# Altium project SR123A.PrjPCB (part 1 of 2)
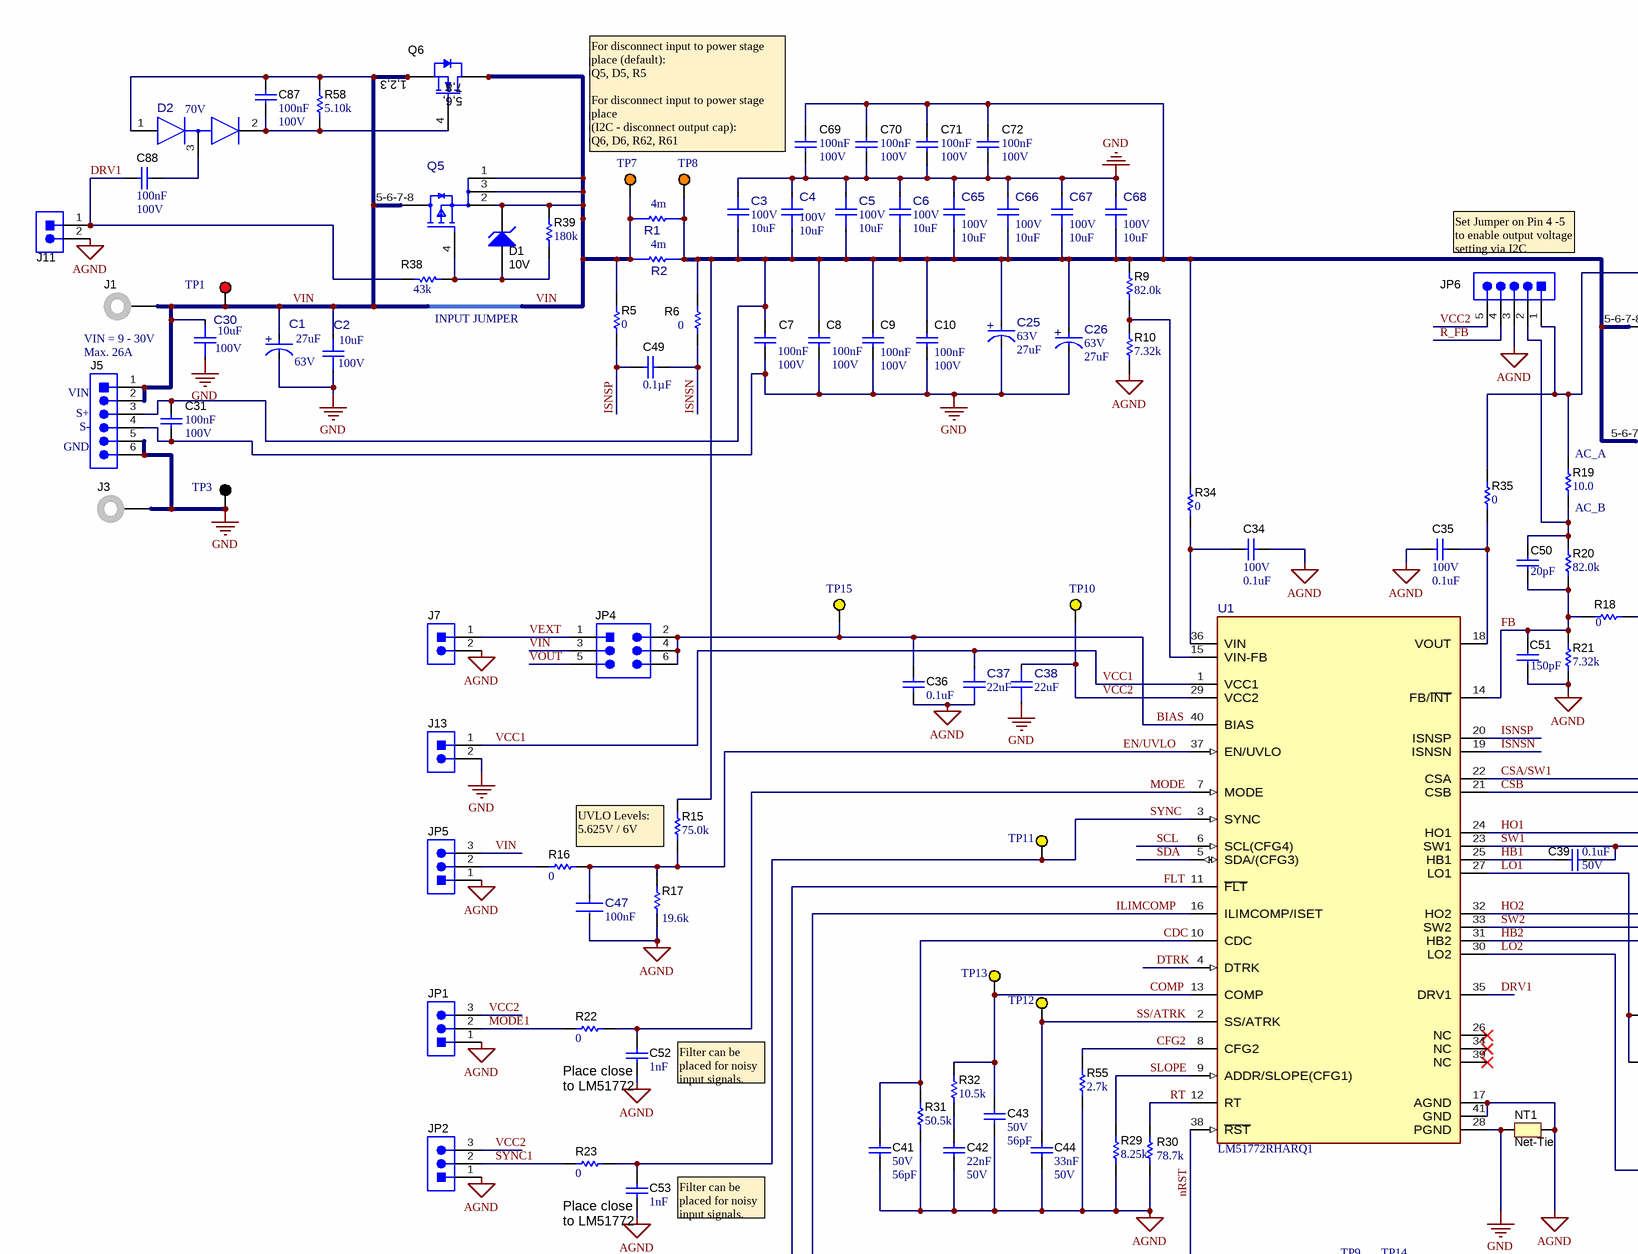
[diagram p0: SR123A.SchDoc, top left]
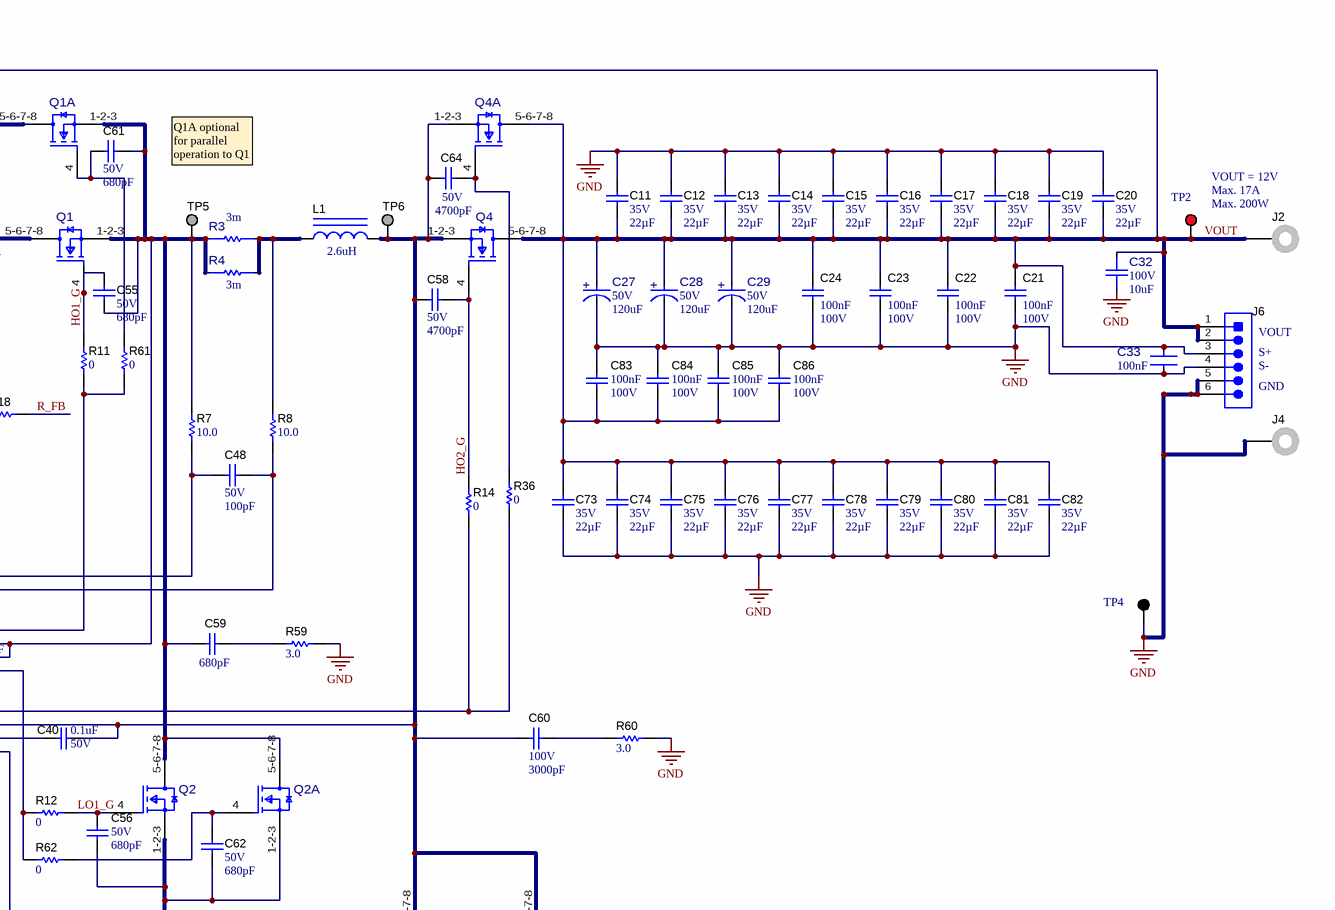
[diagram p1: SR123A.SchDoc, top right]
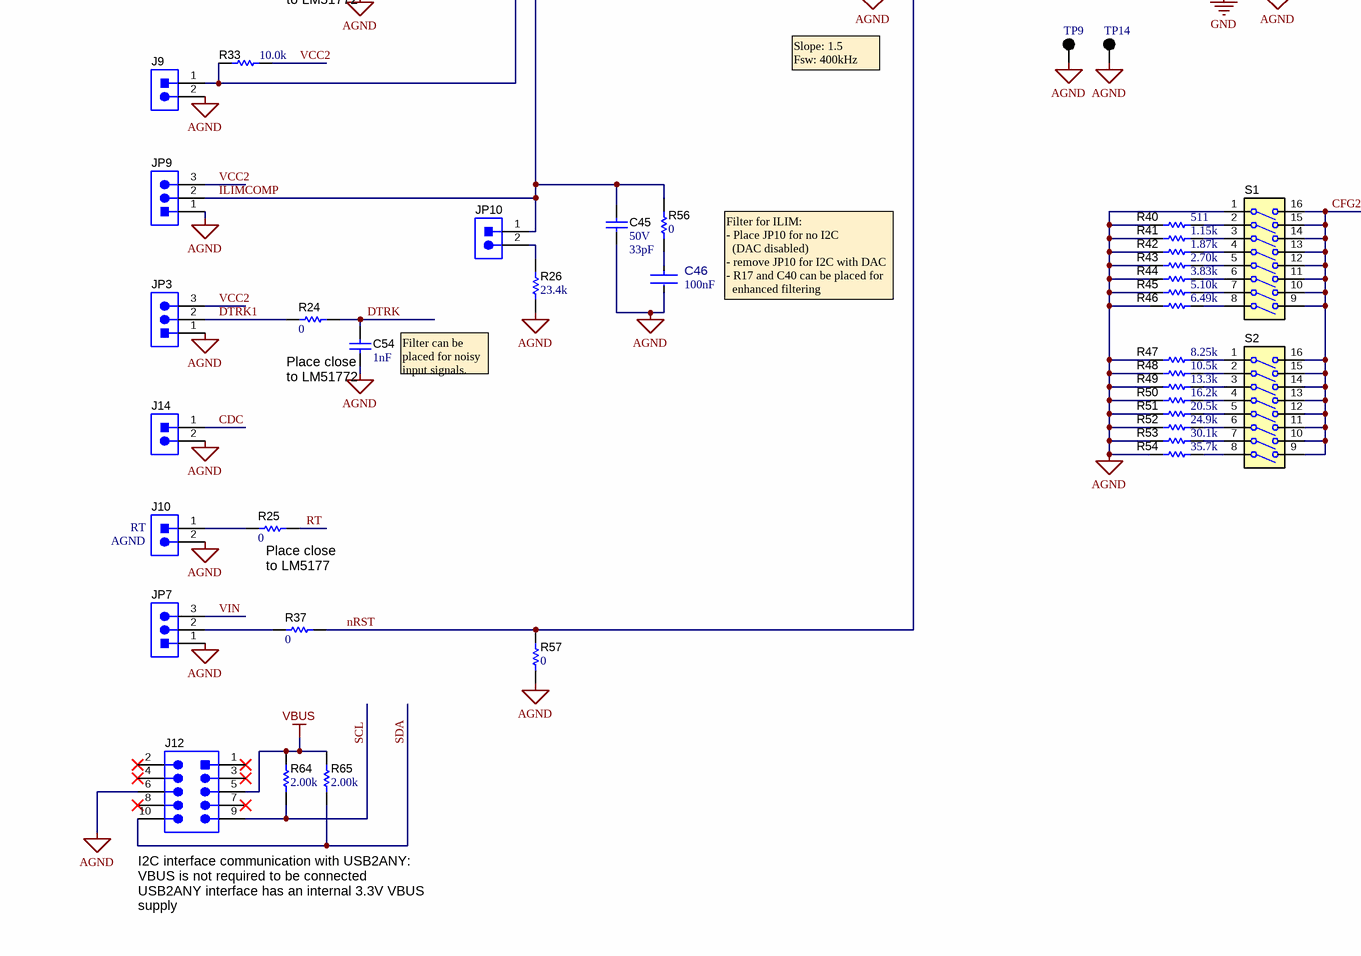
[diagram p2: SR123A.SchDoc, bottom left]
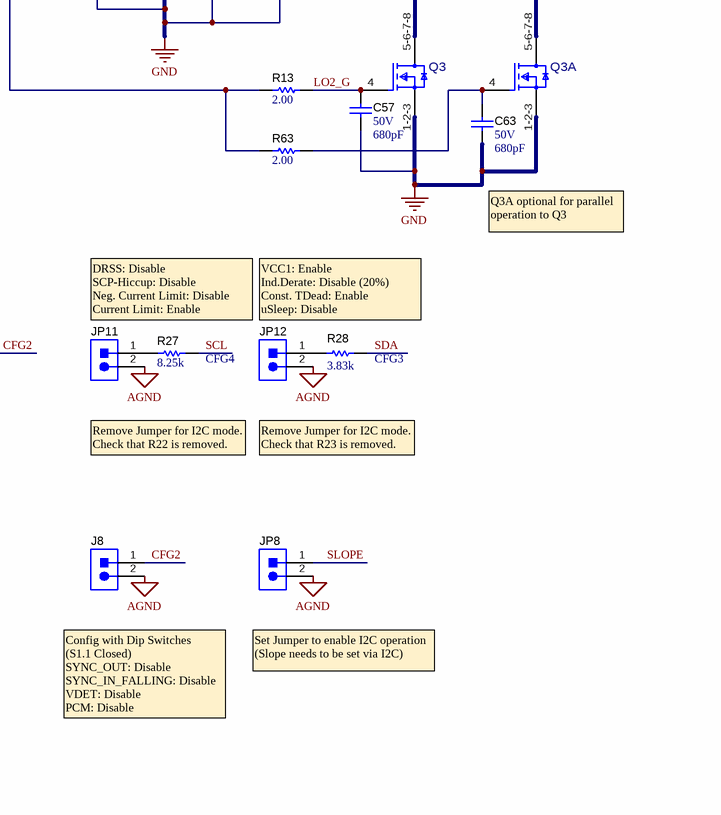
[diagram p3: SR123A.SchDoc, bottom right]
TID: N/A; TechSupport: http://www.ti.com/support; SCH_Rev: A; PRJ_Title: LM51772Q1EVM-HP; PRJ_Number: SR123; PRJ_Customer: Public Release; PCB_Rev: A; CopyrightYear: 2025
3 sheets, 296 parts. Net scope: global (net labels, ports and power ports of the same name join across sheets).
Board file: SR123A.PcbDoc
Sheets:
  SR123A.SchDoc
  SR123A_OptExtLogic.SchDoc
  SR123A_Hardware.SchDoc

## Sheet SR123A.SchDoc: LM51772RWE EVM Schematic
size 558 x 431 mm; Date: Not shown in title block; ApprovedBy: Not shown in title block; CheckedBy: Not shown in title block; Author: Not shown in title block; CompanyName: Not shown in title block; Engineer: Not shown in title block; Organization: Not shown in title block; Address1: Not shown in title block; Address2: Not shown in title block; Address3: Not shown in title block; Address4: Not shown in title block; DocumentNumber: 1; Revision: Use project parameter SCH_Rev; SheetNumber: 1; SheetTotal: 3; PageSetup: Record=PageOptions¦CenterHorizontal=True¦CenterVertical=True¦PrintScale=1.00¦XCorrection=1.00¦YCorrection=1.00¦PrintKind=0¦BorderSize=5000000¦LeftOffset=0¦BottomOffset=0¦Orientation=2¦PaperLength=1000¦PaperWidth=1000¦Scale=100¦PaperSource=15¦PrintQuality=600¦MediaType=1¦DitherType=10¦PaperKind=Letter¦PrintScaleMode=1

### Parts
C1  VDC_V: 63V  ValueDisplayed: 27uF  [FP-A768KE276M1JLAE054_SMT_CAP_8MM3_8MM3-0]  (hidden comment: A768KE276M1JLAE054)
C2  VDC_V: 100V  ValueDisplayed: 10uF  [FP-C3225X7R2A106K250AC_1210-MFG]  (hidden comment: C3225X7R2A106K250AC)
C3  VDC_V: 100V  ValueDisplayed: 10uF  [FP-C3225X7R2A106K250AC_1210-MFG]  (hidden comment: C3225X7R2A106K250AC)
C4  VDC_V: 100V  ValueDisplayed: 10uF  [FP-C3225X7R2A106K250AC_1210-MFG]  (hidden comment: C3225X7R2A106K250AC)
C5  VDC_V: 100V  ValueDisplayed: 10uF  [FP-C3225X7R2A106K250AC_1210-MFG]  (hidden comment: C3225X7R2A106K250AC)
C6  VDC_V: 100V  ValueDisplayed: 10uF  [FP-C3225X7R2A106K250AC_1210-MFG]  (hidden comment: C3225X7R2A106K250AC)
C7  Cap_F: 100nF  VDC_V: 100V  [0603S]  (hidden comment: GCJ188R72A104KA01D)
C8  Cap_F: 100nF  VDC_V: 100V  [0603S]  (hidden comment: GCJ188R72A104KA01D)
C9  Cap_F: 100nF  VDC_V: 100V  [0603S]  (hidden comment: GCJ188R72A104KA01D)
C10  Cap_F: 100nF  VDC_V: 100V  [0603S]  (hidden comment: GCJ188R72A104KA01D)
C11  VDC_V: 35V  ValueDisplayed: 22µF  [1210L]  (hidden comment: GMK325BJ226MM-P)
C12  VDC_V: 35V  ValueDisplayed: 22µF  [1210L]  (hidden comment: GMK325BJ226MM-P)
C13  VDC_V: 35V  ValueDisplayed: 22µF  [1210L]  (hidden comment: GMK325BJ226MM-P)
C14  VDC_V: 35V  ValueDisplayed: 22µF  [1210L]  (hidden comment: GMK325BJ226MM-P)
C15  VDC_V: 35V  ValueDisplayed: 22µF  [1210L]  (hidden comment: GMK325BJ226MM-P)
C16  VDC_V: 35V  ValueDisplayed: 22µF  [1210L]  (hidden comment: GMK325BJ226MM-P)
C17  VDC_V: 35V  ValueDisplayed: 22µF  [1210L]  (hidden comment: GMK325BJ226MM-P)
C18  VDC_V: 35V  ValueDisplayed: 22µF  [1210L]  (hidden comment: GMK325BJ226MM-P)
C19  VDC_V: 35V  ValueDisplayed: 22µF  [1210L]  (hidden comment: GMK325BJ226MM-P)
C20  VDC_V: 35V  ValueDisplayed: 22µF  [1210L]  (hidden comment: GMK325BJ226MM-P)
C21  Cap_F: 100nF  VDC_V: 100V  [0603S]  (hidden comment: GCJ188R72A104KA01D)
C22  Cap_F: 100nF  VDC_V: 100V  [0603S]  (hidden comment: GCJ188R72A104KA01D)
C23  Cap_F: 100nF  VDC_V: 100V  [0603S]  (hidden comment: GCJ188R72A104KA01D)
C24  Cap_F: 100nF  VDC_V: 100V  [0603S]  (hidden comment: GCJ188R72A104KA01D)
C25  VDC_V: 63V  ValueDisplayed: 27uF  [FP-A768KE276M1JLAE054_SMT_CAP_8MM3_8MM3-0]  (hidden comment: A768KE276M1JLAE054)
C26  VDC_V: 63V  ValueDisplayed: 27uF  [FP-A768KE276M1JLAE054_SMT_CAP_8MM3_8MM3-0]  (hidden comment: A768KE276M1JLAE054)
C27  VDC_V: 50V  ValueDisplayed: 120uF  [FP-A768MS127M1HLAE024_SMT_CAP_10MM3_10MM3-MFG]  (hidden comment: A768MS127M1HLAE024)
C28  VDC_V: 50V  ValueDisplayed: 120uF  [FP-A768MS127M1HLAE024_SMT_CAP_10MM3_10MM3-MFG]  (hidden comment: A768MS127M1HLAE024)
C29  VDC_V: 50V  ValueDisplayed: 120uF  [FP-A768MS127M1HLAE024_SMT_CAP_10MM3_10MM3-MFG]  (hidden comment: A768MS127M1HLAE024)
C30  VDC_V: 100V  ValueDisplayed: 10uF  [FP-C3225X7R2A106K250AC_1210-MFG]  (hidden comment: C3225X7R2A106K250AC)
C31  Cap_F: 100nF  VDC_V: 100V  [0603S]  (hidden comment: GCJ188R72A104KA01D)
C32  VDC_V: 100V  ValueDisplayed: 10uF  [FP-C3225X7R2A106K250AC_1210-MFG]  (hidden comment: C3225X7R2A106K250AC)
C33  Cap_F: 100nF  [FP-GCM188L81H104KA57D_0603-MFG]  (hidden comment: GCM188L81H104KA57D)
C34  VDC_V: 100V  ValueDisplayed: 0.1uF  [0402S]  (hidden comment: GRM155R62A104KE14D)
C35  VDC_V: 100V  ValueDisplayed: 0.1uF  [0402S]  (hidden comment: GRM155R62A104KE14D)
C36  ValueDisplayed: 0.1uF  [0603S]  (hidden comment: CGA3E3X7S2A104K080AB)
C37  ValueDisplayed: 22uF  [0603S]  (hidden comment: GRT188R61A226ME13D)
C38  ValueDisplayed: 22uF  [0603S]  (hidden comment: GRT188R61A226ME13D)
C39  VDC_V: 50V  ValueDisplayed: 0.1uF  [0402S]  (hidden comment: GCM155R71H104KE02D)
C40  VDC_V: 50V  ValueDisplayed: 0.1uF  [0402S]  (hidden comment: GCM155R71H104KE02D)
C41  VDC_V: 50V  ValueDisplayed: 56pF  [0603S]  (hidden comment: 06035A560FAT2A)
C42  Cap_F: 22nF  VDC_V: 50V  [0603S]  (hidden comment: C0603X223K5RACTU)
C43  VDC_V: 50V  ValueDisplayed: 56pF  [0603S]  (hidden comment: 06035A560JAT2A)
C44  Cap_F: 33nF  VDC_V: 50V  [0603S]  (hidden comment: 06035C333JAT2A)
C45  VDC_V: 50V  ValueDisplayed: 33pF  [0603S]  (hidden comment: CL10C330FB8NNNC)
C46  Cap_F: 100nF  [FP-GCM188L81H104KA57D_0603-MFG]  (hidden comment: GCM188L81H104KA57D)
C47  Cap_F: 100nF  [FP-GCM188L81H104KA57D_0603-MFG]  (hidden comment: GCM188L81H104KA57D)
C48  VDC_V: 50V  ValueDisplayed: 100pF  [0402S]  (hidden comment: GRM1555C1H101JA01D)
C49  ValueDisplayed: 0.1µF  [0402S]  (hidden comment: 0402BB104KW500)
C50  ValueDisplayed: 20pF  [0603S]  (hidden comment: GRM1885C2A200JA01D)
C51  ValueDisplayed: 150pF  [0603S]  (hidden comment: GRM1885C1H151JA01D)
C52  Cap_F: 1nF  [0603S]  (hidden comment: 06031C102JAT2A)
C53  Cap_F: 1nF  [0603S]  (hidden comment: 06031C102JAT2A)
C54  Cap_F: 1nF  [0603S]  (hidden comment: 06031C102JAT2A)
C55  VDC_V: 50V  ValueDisplayed: 680pF  [0402S]  (hidden comment: GCM1555C1H681FA16D)
C56  VDC_V: 50V  ValueDisplayed: 680pF  [0402S]  (hidden comment: GCM1555C1H681FA16D)
C57  VDC_V: 50V  ValueDisplayed: 680pF  [0402S]  (hidden comment: GCM1555C1H681FA16D)
C58  VDC_V: 50V  ValueDisplayed: 4700pF  [0402S]  (hidden comment: GRM155R71H472KA01D)
C59  ValueDisplayed: 680pF  [0805_HV1]  (hidden comment: GRM2195C2A681JA01D)
C60  VDC_V: 100V  ValueDisplayed: 3000pF  [0805_HV1]  (hidden comment: GRM2165C2A302JA01D)
C61  VDC_V: 50V  ValueDisplayed: 680pF  [0402S]  (hidden comment: GCM1555C1H681FA16D)
C62  VDC_V: 50V  ValueDisplayed: 680pF  [0402S]  (hidden comment: GCM1555C1H681FA16D)
C63  VDC_V: 50V  ValueDisplayed: 680pF  [0402S]  (hidden comment: GCM1555C1H681FA16D)
C64  VDC_V: 50V  ValueDisplayed: 4700pF  [0402S]  (hidden comment: GRM155R71H472KA01D)
C65  VDC_V: 100V  ValueDisplayed: 10uF  [FP-C3225X7R2A106K250AC_1210-MFG]  (hidden comment: C3225X7R2A106K250AC)
C66  VDC_V: 100V  ValueDisplayed: 10uF  [FP-C3225X7R2A106K250AC_1210-MFG]  (hidden comment: C3225X7R2A106K250AC)
C67  VDC_V: 100V  ValueDisplayed: 10uF  [FP-C3225X7R2A106K250AC_1210-MFG]  (hidden comment: C3225X7R2A106K250AC)
C68  VDC_V: 100V  ValueDisplayed: 10uF  [FP-C3225X7R2A106K250AC_1210-MFG]  (hidden comment: C3225X7R2A106K250AC)
C69  Cap_F: 100nF  VDC_V: 100V  [0603S]  (hidden comment: GCJ188R72A104KA01D)
C70  Cap_F: 100nF  VDC_V: 100V  [0603S]  (hidden comment: GCJ188R72A104KA01D)
C71  Cap_F: 100nF  VDC_V: 100V  [0603S]  (hidden comment: GCJ188R72A104KA01D)
C72  Cap_F: 100nF  VDC_V: 100V  [0603S]  (hidden comment: GCJ188R72A104KA01D)
C73  VDC_V: 35V  ValueDisplayed: 22µF  [1210L]  (hidden comment: GMK325BJ226MM-P)
C74  VDC_V: 35V  ValueDisplayed: 22µF  [1210L]  (hidden comment: GMK325BJ226MM-P)
C75  VDC_V: 35V  ValueDisplayed: 22µF  [1210L]  (hidden comment: GMK325BJ226MM-P)
C76  VDC_V: 35V  ValueDisplayed: 22µF  [1210L]  (hidden comment: GMK325BJ226MM-P)
C77  VDC_V: 35V  ValueDisplayed: 22µF  [1210L]  (hidden comment: GMK325BJ226MM-P)
C78  VDC_V: 35V  ValueDisplayed: 22µF  [1210L]  (hidden comment: GMK325BJ226MM-P)
C79  VDC_V: 35V  ValueDisplayed: 22µF  [1210L]  (hidden comment: GMK325BJ226MM-P)
C80  VDC_V: 35V  ValueDisplayed: 22µF  [1210L]  (hidden comment: GMK325BJ226MM-P)
C81  VDC_V: 35V  ValueDisplayed: 22µF  [1210L]  (hidden comment: GMK325BJ226MM-P)
C82  VDC_V: 35V  ValueDisplayed: 22µF  [1210L]  (hidden comment: GMK325BJ226MM-P)
C83  Cap_F: 100nF  VDC_V: 100V  [0603S]  (hidden comment: GCJ188R72A104KA01D)
C84  Cap_F: 100nF  VDC_V: 100V  [0603S]  (hidden comment: GCJ188R72A104KA01D)
C85  Cap_F: 100nF  VDC_V: 100V  [0603S]  (hidden comment: GCJ188R72A104KA01D)
C86  Cap_F: 100nF  VDC_V: 100V  [0603S]  (hidden comment: GCJ188R72A104KA01D)
C87  Cap_F: 100nF  VDC_V: 100V  [0603S]  (hidden comment: GCJ188R72A104KA01D)
C88  Cap_F: 100nF  VDC_V: 100V  [0603S]  (hidden comment: GCJ188R72A104KA01D)
D1  value 10V  [SOD-123]  (hidden comment: MMSZ4697T1G)
D2  Vf_V: 70V  [FP-BAS70-04-E3-18_SOT23-3-MFG]  (hidden comment: BAS70-04-E3-18)
J1  108-0740-001  [Johnson_108-0740-001]  (value not drawn)
J2  108-0740-001  [Johnson_108-0740-001]  (value not drawn)
J3  108-0740-001  [Johnson_108-0740-001]  (value not drawn)
J4  108-0740-001  [Johnson_108-0740-001]  (value not drawn)
J5  61300611121  [WURTH_61300611121]  (value not drawn)
J6  61300611121  [WURTH_61300611121]  (value not drawn)
J7  61300211121  [WURTH_61300211121]  (value not drawn)
J8  61300211121  [WURTH_61300211121]  (value not drawn)
J9  61300211121  [WURTH_61300211121]  (value not drawn)
J10  61300211121  [WURTH_61300211121]  (value not drawn)
J11  61300211121  [WURTH_61300211121]  (value not drawn)
J12  N2510-6002-RB  [CONN_2510-6002]  (value not drawn)
J13  61300211121  [WURTH_61300211121]  (value not drawn)
J14  61300211121  [WURTH_61300211121]  (value not drawn)
JP1  61300311121  [WURTH_61300311121]  (value not drawn)
JP2  61300311121  [WURTH_61300311121]  (value not drawn)
JP3  61300311121  [WURTH_61300311121]  (value not drawn)
JP4  HTSW-103-07-G-D  [Samtec_HTSW-103-07-x-D]  (value not drawn)
JP5  61300311121  [WURTH_61300311121]  (value not drawn)
JP6  61300511121  [Wurth_61300511121]  (value not drawn)
JP7  61300311121  [WURTH_61300311121]  (value not drawn)
JP8  61300211121  [WURTH_61300211121]  (value not drawn)
JP9  61300311121  [WURTH_61300311121]  (value not drawn)
JP10  61300211121  [WURTH_61300211121]  (value not drawn)
JP11  61300211121  [WURTH_61300211121]  (value not drawn)
JP12  61300211121  [WURTH_61300211121]  (value not drawn)
L1  ValueDisplayed: 2.6uH  [WE-HCB_1890]  (hidden comment: 7443556260)
NT1  Net-Tie  [Net-Tie_10mil]  (net tie, no BOM)
Q1  IAUCN04S7L014ATMA1  [FP-IAUCN04S7L014ATMA1_TDSON8-MFG]  (value not drawn)
Q1A  IAUCN04S7L014ATMA1  [FP-IAUCN04S7L014ATMA1_TDSON8-MFG]  (value not drawn)
Q2  IAUCN04S7L014ATMA1  [FP-IAUCN04S7L014ATMA1_TDSON8-MFG]  (value not drawn)
Q2A  IAUCN04S7L014ATMA1  [FP-IAUCN04S7L014ATMA1_TDSON8-MFG]  (value not drawn)
Q3  IAUCN04S7L014ATMA1  [FP-IAUCN04S7L014ATMA1_TDSON8-MFG]  (value not drawn)
Q3A  IAUCN04S7L014ATMA1  [FP-IAUCN04S7L014ATMA1_TDSON8-MFG]  (value not drawn)
Q4  IAUCN04S7L014ATMA1  [FP-IAUCN04S7L014ATMA1_TDSON8-MFG]  (value not drawn)
Q4A  IAUCN04S7L014ATMA1  [FP-IAUCN04S7L014ATMA1_TDSON8-MFG]  (value not drawn)
Q5  SI7155DP-T1-GE3  [FP-SI7155DP-T1-GE3_PowerPAK-SO8-MFG]  (value not drawn)
Q6  CSD18540Q5B  [DNK0008A]  (value not drawn)
R1  value 4m  [FP-KRL2012E-M-R004-F-T5_2012-MFG]  (hidden comment: KRL2012E-M-R004-F-T5)
R2  value 4m  [FP-KRL2012E-M-R004-F-T5_2012-MFG]  (hidden comment: KRL2012E-M-R004-F-T5)
R3  value 3m  [FP-KRL2012E-M-R003-F-T5_0805-MFG]  (hidden comment: KRL2012E-M-R003-F-T5)
R4  value 3m  [FP-KRL2012E-M-R003-F-T5_0805-MFG]  (hidden comment: KRL2012E-M-R003-F-T5)
R5  ValueDisplayed: 0  [0603S]  (hidden comment: RMCF0603ZT0R00)
R6  ValueDisplayed: 0  [0603S]  (hidden comment: RMCF0603ZT0R00)
R7  ValueDisplayed: 10.0  [0603S]  (hidden comment: CRCW060310R0FKEAHP)
R8  ValueDisplayed: 10.0  [0603S]  (hidden comment: CRCW060310R0FKEAHP)
R9  ValueDisplayed: 82.0k  [0603S]  (hidden comment: RC0603FR-0782KL)
R10  ValueDisplayed: 7.32k  [0603S]  (hidden comment: CRCW06037K32FKEA)
R11  ValueDisplayed: 0  [0603S]  (hidden comment: RMCF0603ZT0R00)
R12  ValueDisplayed: 0  [0603S]  (hidden comment: RMCF0603ZT0R00)
R13  ValueDisplayed: 2.00  [0603S]  (hidden comment: MCT06030C2008FP500)
R14  ValueDisplayed: 0  [0603S]  (hidden comment: RMCF0603ZT0R00)
R15  ValueDisplayed: 75.0k  [0603S]  (hidden comment: RC0603FR-0775KL)
R16  ValueDisplayed: 0  [0603S]  (hidden comment: RMCF0603ZT0R00)
R17  ValueDisplayed: 19.6k  [0603S]  (hidden comment: CRCW060319K6FKEA)
R18  ValueDisplayed: 0  [0603S]  (hidden comment: RMCF0603ZT0R00)
R19  ValueDisplayed: 10.0  [0603S]  (hidden comment: RC0603FR-0710RL)
R20  ValueDisplayed: 82.0k  [0603S]  (hidden comment: RC0603FR-0782KL)
R21  ValueDisplayed: 7.32k  [0603S]  (hidden comment: CRCW06037K32FKEA)
R22  ValueDisplayed: 0  [0603S]  (hidden comment: RMCF0603ZT0R00)
R23  ValueDisplayed: 0  [0603S]  (hidden comment: RMCF0603ZT0R00)
R24  ValueDisplayed: 0  [0603S]  (hidden comment: RMCF0603ZT0R00)
R25  ValueDisplayed: 0  [0603S]  (hidden comment: RMCF0603ZT0R00)
R26  ValueDisplayed: 23.4k  [0603S]  (hidden comment: RT0603BRD0723K4L)
R27  ValueDisplayed: 8.25k  [0603S]  (hidden comment: RC0603FR-078K25L)
R28  ValueDisplayed: 3.83k  [0603S]  (hidden comment: CRCW06033K83FKEA)
R29  ValueDisplayed: 8.25k  [0603S]  (hidden comment: RC0603FR-078K25L)
R30  ValueDisplayed: 78.7k  [0603S]  (hidden comment: CRCW060378K7FKEA)
R31  ValueDisplayed: 50.5k  [0603S]  (hidden comment: RT0603BRD0750K5L)
R32  ValueDisplayed: 10.5k  [0603S]  (hidden comment: CRCW060310K5FKEA)
R33  ValueDisplayed: 10.0k  [0603S]  (hidden comment: RT0603BRD0710KL)
R34  ValueDisplayed: 0  [0603S]  (hidden comment: RMCF0603ZT0R00)
R35  ValueDisplayed: 0  [0603S]  (hidden comment: RMCF0603ZT0R00)
R36  ValueDisplayed: 0  [0603S]  (hidden comment: RMCF0603ZT0R00)
R37  ValueDisplayed: 0  [0603S]  (hidden comment: RMCF0603ZT0R00)
R38  ValueDisplayed: 43k  [0603S]  (hidden comment: CRCW060343K0JNEA)
R39  ValueDisplayed: 180k  [0603S]  (hidden comment: CRCW0603180KJNEA)
R40  ValueDisplayed: 511  [0603S]  (hidden comment: CRCW0603511RFKEA)
R41  ValueDisplayed: 1.15k  [0603S]  (hidden comment: CRCW06031K15FKEA)
R42  ValueDisplayed: 1.87k  [0603S]  (hidden comment: RC0603FR-071K87L)
R43  ValueDisplayed: 2.70k  [0603S]  (hidden comment: RC0603FR-072K7L)
R44  ValueDisplayed: 3.83k  [0603S]  (hidden comment: CRCW06033K83FKEA)
R45  ValueDisplayed: 5.10k  [0603S]  (hidden comment: RC0603FR-075K1L)
R46  ValueDisplayed: 6.49k  [0603S]  (hidden comment: RC0603FR-076K49L)
R47  ValueDisplayed: 8.25k  [0603S]  (hidden comment: RC0603FR-078K25L)
R48  ValueDisplayed: 10.5k  [0603S]  (hidden comment: CRCW060310K5FKEA)
R49  ValueDisplayed: 13.3k  [0603S]  (hidden comment: RC0603FR-0713K3L)
R50  ValueDisplayed: 16.2k  [0603S]  (hidden comment: CRCW060316K2FKEA)
R51  ValueDisplayed: 20.5k  [0603S]  (hidden comment: RC0603FR-0720K5L)
R52  ValueDisplayed: 24.9k  [0603S]  (hidden comment: CRCW060324K9FKEA)
R53  ValueDisplayed: 30.1k  [0603S]  (hidden comment: CRCW060330K1FKEA)
R54  ValueDisplayed: 35.7k  [0603S]  (hidden comment: CRCW060335K7FKEA)
R55  ValueDisplayed: 2.7k  [0603S]  (hidden comment: CRCW06032K70JNEA)
R56  ValueDisplayed: 0  [0603S]  (hidden comment: RMCF0603ZT0R00)
R57  ValueDisplayed: 0  [0603S]  (hidden comment: RMCF0603ZT0R00)
R58  ValueDisplayed: 5.10k  [0603S]  (hidden comment: RC0603FR-075K1L)
R59  ValueDisplayed: 3.0  [0603S]  (hidden comment: CRCW06033R00JNEA)
R60  ValueDisplayed: 3.0  [0603S]  (hidden comment: CRCW06033R00JNEA)
R61  ValueDisplayed: 0  [0603S]  (hidden comment: RMCF0603ZT0R00)
R62  ValueDisplayed: 0  [0603S]  (hidden comment: RMCF0603ZT0R00)
R63  ValueDisplayed: 2.00  [0603S]  (hidden comment: MCT06030C2008FP500)
R64  ValueDisplayed: 2.00k  [0603S]  (hidden comment: RC0603FR-072KL)
R65  ValueDisplayed: 2.00k  [0603S]  (hidden comment: RC0603FR-072KL)
S1  218-8LPST  [SW_218-8LP]  (value not drawn)
S2  218-8LPST  [SW_218-8LP]  (value not drawn)
TP1  5010  [Keystone5010]  (value not drawn)
TP2  5010  [Keystone5010]  (value not drawn)
TP3  5011  [Keystone5011]  (value not drawn)
TP4  5011  [Keystone5011]  (value not drawn)
TP5  S2761-46R  [Harwin_S2761-46R]  (value not drawn)
TP6  S2761-46R  [Harwin_S2761-46R]  (value not drawn)
TP7  5013  [Keystone5013]  (value not drawn)
TP8  5013  [Keystone5013]  (value not drawn)
TP9  5001  [Keystone5001]  (value not drawn)
TP10  5004  [Keystone5004]  (value not drawn)
TP11  5004  [Keystone5004]  (value not drawn)
TP12  5004  [Keystone5004]  (value not drawn)
TP13  5004  [Keystone5004]  (value not drawn)
TP14  5001  [Keystone5001]  (value not drawn)
TP15  5004  [Keystone5004]  (value not drawn)
U1  LM51772RHARQ1  [RHA0040P-MFG]

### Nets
AGND: C34.1 C35.2 C36.1 C37.1 C41.2 C42.2 C43.2 C44.2 C45.2 C46.2 C47.2 C51.2 C52.2 C53.2 C54.2 J7.2 J8.2 J9.2 J10.2 J11.2 J12.6 J14.2 JP1.1 JP2.1 JP3.1 JP5.1 JP6.3 JP7.1 JP8.2 JP9.1 JP11.2 JP12.2 NT1.2 R10.1 R17.1 R21.1 R26.1 R29.1 R30.1 R31.1 R40.1 R41.1 R42.1 R43.1 R44.1 R45.1 R46.1 R47.1 R48.1 R49.1 R50.1 R51.1 R52.1 R53.1 R54.1 R55.1 R57.2 S1.1 TP9.1 TP14.1 U1.17(AGND) U1.41(GND)
GND: C1.1(CATHODE) C2.1 C3.2 C4.2 C5.2 C6.2 C7.2 C8.2 C9.2 C10.2 C11.1 C12.1 C13.1 C14.1 C15.2 C16.2 C17.2 C18.2 C19.2 C20.2 C21.2 C22.2 C23.2 C24.2 C25.1(CATHODE) C26.1(CATHODE) C27.1(CATHODE) C28.1(CATHODE) C29.1(CATHODE) C30.1 C31.2 C32.1 C33.2 C38.1 C56.2 C57.2 C62.2 C63.2 C65.2 C66.2 C67.2 C68.2 C69.2 C70.2 C71.2 C72.2 C73.1 C74.1 C75.1 C76.1 C77.2 C78.1 C79.2 C80.2 C81.1 C82.2 C83.1 C84.1 C85.1 C86.1 J3.1 J4.1 J5.4 J5.5 J5.6 J6.4 J6.5 J6.6 J13.2 NT1.1 Q2.1-2-3(S) Q2A.1-2-3(S) Q3.1-2-3(S) Q3A.1-2-3(S) R59.1 R60.1 TP3.1 TP4.1 U1.28(PGND)
VBUS: J12.5 R64.2 R65.2
VCC1: C37.2 J13.1 U1.1(VCC1)
BIAS: C36.2 JP4.2 JP4.4 JP4.6 TP15.1 U1.40(BIAS)
CDC: C41.1 J14.1 R31.2 U1.10(CDC)
CFG2: J8.1 R55.2 S1.9(8A) S1.10(7A) S1.11(6A) S1.12(5A) S1.13(4A) S1.14(3A) S1.15(2A) S1.16(1A) S2.9(8A) S2.10(7A) S2.11(6A) S2.12(5A) S2.13(4A) S2.14(3A) S2.15(2A) S2.16(1A) U1.8(CFG2)
COMP: C43.1 R32.2 TP13.1 U1.13(COMP)
CSA/SW1: C48.2 R7.1 U1.22(CSA)
CSB: C48.1 R8.1 U1.21(CSB)
DRV1: C88.1 J11.1 R38.1 U1.35(DRV1)
DTRK: C54.1 R24.2 U1.4(DTRK)
DTRK1: JP3.2 R24.1
EN/UVLO: C47.1 R15.1 R16.1 R17.2 U1.37(EN/UVLO)
FB: C50.2 C51.1 R18.1 R20.1 R21.2 U1.14(FB/~{INT})
FLT: J9.1 R33.1 U1.11(~{FLT})
HB1: C39.2 U1.25(HB1)
HB2: C40.2 U1.31(HB2)
HO1: R11.1 R61.1 U1.24(HO1)
HO1_G: C55.1 Q1.4(G) R11.2
HO2: R14.1 R36.1 U1.32(HO2)
HO2_G: C58.2 Q4.4(G) R14.2
ILIMCOMP: C45.1 JP9.2 JP10.1 R56.2 U1.16(ILIMCOMP/ISET)
ISNSN: C49.1 R6.1 U1.19(ISNSN)
ISNSP: C49.2 R5.1 U1.20(ISNSP)
LO1: R12.1 R62.1 U1.27(LO1)
LO1_G: C56.1 Q2.4(G) R12.2
LO2: R13.1 R63.1 U1.30(LO2)
LO2_G: C57.1 Q3.4(G) R13.2
MODE: C52.1 R22.2 U1.7(MODE)
MODE1: JP1.2 R22.1
nRST: R37.1 R57.1 U1.38(~{RST})
R_FB: JP6.4 R18.2
RT: R25.1 R30.2 U1.12(RT)
SCL: J12.9 R27.2 R64.1 U1.6(SCL(CFG4))
SDA: J12.10 R28.2 R65.1 U1.5(SDA/(CFG3))
SLOPE: JP8.1 R29.2 U1.9(ADDR/SLOPE(CFG1))
SS/ATRK: C44.1 TP12.1 U1.2(SS/ATRK)
SW1: C39.1 C55.2 C59.2 C61.2 Q1.1-2-3(S) Q1A.1-2-3(S) Q2.5-6-7-8(D) Q2A.5-6-7-8(D) R3.1 R4.1 R7.2 TP5.1 U1.23(SW1)
SW2: C40.1 C58.1 C60.2 C64.1 L1.2 Q3.5-6-7-8(D) Q3A.5-6-7-8(D) Q4.1-2-3(S) Q4A.1-2-3(S) TP6.1 U1.33(SW2)
SYNC: C53.1 R23.2 TP11.1 U1.3(SYNC)
SYNC1: JP2.2 R23.1
VCC2: C38.2 JP1.3 JP2.3 JP3.3 JP6.5 JP9.3 R33.2 TP10.1 U1.29(VCC2)
VEXT: J7.1 JP4.1
VIN: C1.2(ANODE) C2.2 C30.2 C87.2 D1.1(K) D2.1(1_ANODE) J1.1 J5.1 J5.2 JP4.3 JP5.3 JP7.3 Q5.1(S) Q5.2(S) Q5.3(S) Q5.5-6-7-8(D) Q6.1(S) Q6.2(S) Q6.3(S) Q6.5(D) Q6.6(D) Q6.7(D) Q6.8(D) Q6.9(D) R1.1 R2.1 R5.2 R39.2 R58.2 TP1.1 TP7.1
VOUT: C11.2 C12.2 C13.2 C14.2 C15.1 C16.1 C17.1 C18.1 C19.1 C20.1 C21.1 C22.1 C23.1 C24.1 C27.2(ANODE) C28.2(ANODE) C29.2(ANODE) C32.2 C33.1 C73.2 C74.2 C75.2 C76.2 C77.1 C78.2 C79.1 C80.1 C81.2 C82.1 C83.2 C84.2 C85.2 C86.2 J2.1 J6.1 J6.2 J6.3 JP4.5 JP6.1 Q4.5-6-7-8(D) Q4A.5-6-7-8(D) R19.2 R35.2 TP2.1
NetC3_1: C3.1 C4.1 C5.1 C6.1 C7.1 C8.1 C9.1 C10.1 C25.2(ANODE) C26.2(ANODE) C31.1 C65.1 C66.1 C67.1 C68.1 C69.1 C70.1 C71.1 C72.1 J5.3 Q1.5-6-7-8(D) Q1A.5-6-7-8(D) R1.2 R2.2 R6.2 R9.2 R15.2 R34.2 TP8.1
NetC34_2: C34.2 R34.1 U1.36(VIN)
NetC35_1: C35.1 R35.1 U1.18(VOUT)
NetC42_1: C42.1 R32.1
NetC46_1: C46.1 R56.1
NetC50_1: C50.1 JP6.2 R19.1 R20.2
NetC59_1: C59.1 R59.2
NetC60_1: C60.1 R60.2
NetC61_1: C61.1 Q1A.4(G) R61.2
NetC62_1: C62.1 Q2A.4(G) R62.2
NetC63_1: C63.1 Q3A.4(G) R63.2
NetC64_2: C64.2 Q4A.4(G) R36.2
NetC87_1: C87.1 D2.2(2_CATHODE) Q6.4(G) R58.1
NetC88_2: C88.2 D2.3(1_CATHODE/2_ANODE)
NetD1_2: D1.2(A) Q5.4(G) R38.2 R39.1
NetJ10_1: J10.1 R25.2
NetJP5_2: JP5.2 R16.2
NetJP7_2: JP7.2 R37.2
NetJP10_2: JP10.2 R26.2
NetJP11_1: JP11.1 R27.1
NetJP12_1: JP12.1 R28.1
NetL1_1: L1.1 R3.2 R4.2 R8.2
NetR9_1: R9.1 R10.2 U1.15(VIN-FB)
NetR40_2: R40.2 S1.2
NetR41_2: R41.2 S1.3
NetR42_2: R42.2 S1.4
NetR43_2: R43.2 S1.5
NetR44_2: R44.2 S1.6
NetR45_2: R45.2 S1.7
NetR46_2: R46.2 S1.8
NetR47_2: R47.2 S2.1
NetR48_2: R48.2 S2.2
NetR49_2: R49.2 S2.3
NetR50_2: R50.2 S2.4
NetR51_2: R51.2 S2.5
NetR52_2: R52.2 S2.6
NetR53_2: R53.2 S2.7
NetR54_2: R54.2 S2.8

Not connected (* = marked no-connect by the designer): J12 1* 2* 3* 4* 7* 8*; U1 26(NC)* 34(NC)* 39(NC)*

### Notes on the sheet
- For disconnect input to power stage place (default):
  Q5, D5, R5
  For disconnect input to power stage place
  (I2C - disconnect output cap):
  Q6, D6, R62, R61
- (near JP6) Set Jumper on Pin 4 -5 to enable output voltage setting via I2C
- VIN = 9 - 30V
- Max. 26A
- (near R38) INPUT JUMPER
- Q1A optional for parallel operation to Q1
- (near J5) VIN
- (near J5) S+
- (near J5) S-
- VOUT = 12V
- Max. 17A
- Max. 200W
- (near J5) GND
- (near R19) AC_A
- (near R19) AC_B
- (near J6) VOUT
- (near J6) S+
- (near J6) S-
- GND
- UVLO Levels:
  5.625V / 6V
- (near C52) Place close
  to LM51772
- (near C52) Filter can be placed for noisy input signals.
- (near C53) Place close
  to LM51772
- (near C53) Filter can be placed for noisy input signals.
- Slope: 1.5
  Fsw: 400kHz
- Q3A optional for parallel operation to Q3
- DRSS: Disable
  SCP-Hiccup: Disable
  Neg. Current Limit: Disable
  Current Limit: Enable
- (near R27) CFG4
- VCC1: Enable
  Ind.Derate: Disable (20%)
  Const. TDead: Enable
  uSleep: Disable
- (near R28) CFG3
- Filter for ILIM:
  - Place JP10 for no I2C
  (DAC disabled)
  - remove JP10 for I2C with DAC
  - R17 and C40 can be placed for
  enhanced filtering
- Remove Jumper for I2C mode.
  Check that R22 is removed.
- Remove Jumper for I2C mode.
  Check that R23 is removed.
- (near C54) Place close
  to LM51772
- Filter can be placed for noisy input signals.
- (near J10) AGND
- (near J10) RT
- (near R25) Place close
  to LM5177
- Config with Dip Switches
  (S1.1 Closed)
  SYNC_OUT: Disable
  SYNC_IN_FALLING: Disable
  VDET: Disable
  PCM: Disable
- Set Jumper to enable I2C operation
  (Slope needs to be set via I2C)
- (near J12) I2C interface communication with USB2ANY:
  VBUS is not required to be connected
  USB2ANY interface has an internal 3.3V VBUS supply

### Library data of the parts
C1 C25 C26 = CMP-0097690-1: Cap Aluminum Polymer 27uF 63V 20% Solder Cylindrical 54m Ohm 1175mA 2000 hr 125°C T/R; Manufacturer: KEMET; Life: 2000Hours; Cap_F: 27µF; Value: 27µF; Leakage Current: 340uA; SizeZ_mm: 7mm; IRMS_A: 1.175A; AEC Qualified: No
C2-C6 C30 C32 C65-C68 = CMP-0096021-1: 10 µF ±10% 100V Ceramic Capacitor X7R 1210 (3225 Metric); Manufacturer: TDK; Cap_F: 10µF; AEC Qualified: No; Value: 10µF; SizeZ_mm: 2.85mm; TempCo: 15%
C7-C10 C21-C24 C31 C69-C72 C83-C88 = CMP-0064935-4: CAP, CERM, 0.1 uF, 100 V,+/- 10%, X7R, AEC-Q200 Grade 1, 0603; Manufacturer: MuRata; TaMin_C: -55°C; Polarized: N; SizeAreaWB_mm2: 4.68; Value1: Unknown; U/M: EA; Value: 0.1uF; TaMax_C: 125°C; SizeZ_mm: 1; SizeX_mm: 1.6; SizeY_mm: 0.8; Cap_Case: 0603; SizeArea_mm2: 1.28; AEC Qualified: Y; AEC Category: Q200
C11-C20 C73-C82 = CMP-0085817-1: CAP, CERM, 22 µF, 35 V,+/- 20%, X5R, 1210; Manufacturer: Taiyo Yuden; Value: 22uF; SizeZ_mm: 1.35; Cap_Case: 1210; TaMax_C: 85°C; U/M: EA; SizeAreaWB_mm2: 14.7; SizeX_mm: 3.2; SizeArea_mm2: 8; TaMin_C: -55°C; AEC Qualified: N; SizeY_mm: 2.5; AEC Category: Q200
C27-C29 = CMP-0097021-1: 120 µF 50 V Aluminum - Polymer Capacitors Radial, Can - SMD 24mOhm 2000 Hrs @ 125°C; Manufacturer: KEMET; Cap_F: 120µF; AEC Qualified: No; IRMS_A: 2.15A; Life: 2000Hours; Value: 120µF; Leakage Current: 1200uA; SizeZ_mm: 12.7mm; Tolerance_%: 20%; Esr: 24m
C33 C46 C47 = CMP-0086535-1: 0.1µF ±10% 50V Ceramic Capacitor X8L 0603 (1608 Metric); Manufacturer: Murata Electronics North America; Symbol Name: SYM-GCM188L81H104KA57D; AEC Qualified: Yes; TempCo: -40+15%; SizeZ_mm: 0.9mm; AEC Grade: Grade 0
C34 C35 = CMP-0006618-2: CAP, CERM, 0.1 uF, 100 V, +/- 10%, X5R, 0402; Manufacturer: MuRata; TaMin_C: -55°C; Polarized: N; SizeAreaWB_mm2: 3; Value1: Unknown; U/M: EA; Value: 0.1uF; TaMax_C: 85°C; SizeZ_mm: 0.6; SizeX_mm: 1; SizeY_mm: 0.5; Cap_Case: 0402; Cap_F: 100nF; AEC Category: Q200
C36 = CMP-0007099-4: CAP, CERM, 0.1 uF, 100 V, +/- 10%, X7S, AEC-Q200 Grade 1, 0603; Manufacturer: TDK; TaMin_C: -55°C; ESR_ohm: 0.04959; Polarized: N; SizeAreaWB_mm2: 4.68; Value1: 0.04959 ohm; U/M: EA; Value: 0.1uF; TaMax_C: 125°C; SizeZ_mm: 1; SizeX_mm: 1.6; SizeY_mm: 0.8; Cap_Case: 0603; Value2: 100V; SizeArea_mm2: 1.28; AEC Qualified: Y; Cap_F: 100nF; IRMS_A: 7.51618dA; AEC Category: Q200
C37 C38 = CMP-0092433-2: Multi-Layer Ceramic Capacitor 22uF 10V X5R ±20% 0603 Paper T/R; Manufacturer: Murata; Cap_F: 22µF; Value: 22µF; SizeZ_mm: 1mm; AEC Qualified: Yes; AEC Grade: Grade 3; TempCo: 15%
C39 C40 = CMP-0006356-2: CAP, CERM, 0.1 uF, 50 V, +/- 10%, X7R, AEC-Q200 Grade 1, 0402; Manufacturer: MuRata; TaMin_C: -55°C; Polarized: N; SizeAreaWB_mm2: 3; Value1: Unknown; U/M: EA; Value: 0.1uF; TaMax_C: 125°C; SizeZ_mm: 0.6; SizeX_mm: 1; SizeY_mm: 0.5; Cap_Case: 0402; AEC Qualified: Y; Cap_F: 100nF; AEC Category: Q200
C41 = CMP-0006792-4: CAP, CERM, 56 pF, 50 V, +/- 1%, C0G/NP0, 0603; Manufacturer: AVX; TaMin_C: -55°C; Polarized: N; SizeAreaWB_mm2: 4.68; Value1: Unknown; U/M: EA; Value: 56pF; TaMax_C: 125°C; SizeZ_mm: 1; SizeX_mm: 1.6; SizeY_mm: 0.8; Cap_Case: 0603; SizeArea_mm2: 1.28; AEC Category: Q200
C42 = CMP-0006984-4: CAP, CERM, 0.022 uF, 50 V, +/- 10%, X7R, 0603; Manufacturer: Kemet; TaMin_C: -55°C; Polarized: N; SizeAreaWB_mm2: 4.68; Value1: Unknown; U/M: EA; TaMax_C: 125°C; SizeZ_mm: 1; SizeX_mm: 1.6; SizeY_mm: 0.8; Cap_Case: 0603; SizeArea_mm2: 1.28; AEC Category: Q200
C43 = CMP-0006793-4: CAP, CERM, 56 pF, 50 V, +/- 5%, C0G/NP0, 0603; Manufacturer: AVX; TaMin_C: -55°C; ESR_ohm: 0.159; Polarized: N; SizeAreaWB_mm2: 4.68; Value1: 0.159 ohm; U/M: EA; Value: 56pF; TaMax_C: 125°C; SizeZ_mm: 1; SizeX_mm: 1.6; SizeY_mm: 0.8; Cap_Case: 0603; SizeArea_mm2: 1.28; AEC Category: Q200
C44 = CMP-0006806-4: CAP, CERM, 0.033 uF, 50 V, +/- 5%, X7R, 0603; Manufacturer: AVX; TaMin_C: -55°C; Polarized: N; SizeAreaWB_mm2: 4.68; Value1: Unknown; U/M: EA; TaMax_C: 125°C; SizeZ_mm: 1; SizeX_mm: 1.6; SizeY_mm: 0.8; Cap_Case: 0603; SizeArea_mm2: 1.28; AEC Category: Q200
C45 = CMP-0007117-4: CAP, CERM, 33 pF, 50 V, +/- 5%, C0G/NP0, 0603; Manufacturer: Samsung Electro-Mechanics; TaMin_C: -55°C; Polarized: N; SizeAreaWB_mm2: 4.68; Value1: Unknown; U/M: EA; Value: 33pF; TaMax_C: 125°C; SizeZ_mm: 1; SizeX_mm: 1.6; SizeY_mm: 0.8; Cap_Case: 0603; SizeArea_mm2: 1.28; AEC Category: Q200
C48 = CMP-0006410-2: CAP, CERM, 100 pF, 50 V, +/- 5%, C0G/NP0, 0402; Manufacturer: MuRata; TaMin_C: -55°C; Polarized: N; SizeAreaWB_mm2: 3; Value1: Unknown; U/M: EA; Value: 100pF; TaMax_C: 125°C; SizeZ_mm: 0.6; SizeX_mm: 1; SizeY_mm: 0.5; Cap_Case: 0402; AEC Category: Q200
C49 = CMP-0860983-1: CAP, CERM, 0.1 µF, 50 V,+/- 10%, X7R, 0402; Manufacturer: Passive Plus; Cap_Case: 0402; TaMax_C: 125°C; VDC_V: 50V; U/M: EA; SizeY_mm: 0.5; TaMin_C: -55°C; SizeAreaWB_mm2: 3; Value: 0.1uF; AEC Qualified: N; SizeX_mm: 1; AEC Category: Q200; SizeZ_mm: 0.6; Cap_F: 100nF
C50 = CMP-0007253-4: CAP, CERM, 20 pF, 100 V, +/- 5%, C0G/NP0, 0603; Manufacturer: MuRata; TaMin_C: -55°C; Polarized: N; SizeAreaWB_mm2: 4.68; Value1: Unknown; U/M: EA; Value: 20pF; TaMax_C: 125°C; SizeZ_mm: 1; SizeX_mm: 1.6; SizeY_mm: 0.8; Cap_Case: 0603; Value2: 100V; SizeArea_mm2: 1.28; AEC Category: Q200
C51 = CMP-0007185-4: CAP, CERM, 150 pF, 50 V, +/- 5%, C0G/NP0, 0603; Manufacturer: MuRata; TaMin_C: -55°C; Polarized: N; SizeAreaWB_mm2: 4.68; Value1: Unknown; U/M: EA; Value: 150pF; TaMax_C: 125°C; SizeZ_mm: 1; SizeX_mm: 1.6; SizeY_mm: 0.8; Cap_Case: 0603; Value2: 50V; SizeArea_mm2: 1.28; AEC Category: Q200
C52-C54 = CMP-0006723-4: CAP, CERM, 1000 pF, 100 V, +/- 5%, X7R, 0603; Manufacturer: AVX; TaMin_C: -55°C; ESR_ohm: 2.76d; Polarized: N; SizeAreaWB_mm2: 4.68; Value1: 0.276 ohm; U/M: EA; Value: 1000pF; TaMax_C: 125°C; SizeZ_mm: 1; SizeX_mm: 1.6; SizeY_mm: 0.8; Cap_Case: 0603; Value2: 100V; SizeArea_mm2: 1.28; AEC Category: Q200
C55-C57 C61-C63 = CMP-0086096-1: CAP, CERM, 680 pF, 50 V,+/- 1%, C0G/NP0, AEC-Q200 Grade 1, 0402; Manufacturer: MuRata; SizeArea_mm2: 0.5; Cap_Case: 0402; Polarized: N; SizeZ_mm: 0.6; SizeAreaWB_mm2: 3; AEC Qualified: Y; Value: 680pF; TaMin_C: -55°C; SizeX_mm: 1; U/M: EA; TaMax_C: 125°C; AEC Category: Q200
C58 C64 = CMP-0006692-2: CAP, CERM, 4700 pF, 50 V, +/- 10%, X7R, 0402; Manufacturer: MuRata; TaMin_C: -55°C; Polarized: N; SizeAreaWB_mm2: 3; Value1: Unknown; U/M: EA; Value: 4700pF; TaMax_C: 125°C; SizeZ_mm: 0.6; SizeX_mm: 1; SizeY_mm: 0.5; Cap_Case: 0402; Cap_F: 4.7nF; AEC Category: Q200
C59 = CMP-0008176-2: CAP, CERM, 680 pF, 100 V, +/- 5%, C0G/NP0, 0805; Manufacturer: MuRata; TaMin_C: -55°C; Polarized: N; SizeAreaWB_mm2: 6.75; Value1: Unknown; U/M: EA; Value: 680pF; TaMax_C: 125°C; SizeZ_mm: 1.45; SizeX_mm: 2; SizeY_mm: 1.25; Cap_Case: 0805; Value2: 100V; SizeArea_mm2: 2.5; AEC Category: Q200
C60 = CMP-0008116-2: CAP, CERM, 3000 pF, 100 V, +/- 5%, C0G/NP0, 0805; Manufacturer: MuRata; TaMin_C: -55°C; Polarized: N; SizeAreaWB_mm2: 6.75; Value1: Unknown; U/M: EA; Value: 3000pF; TaMax_C: 125°C; SizeZ_mm: 1.45; SizeX_mm: 2; SizeY_mm: 1.25; Cap_Case: 0805; SizeArea_mm2: 2.5; Cap_F: 3nF; AEC Category: Q200
D1 = CMP-0005740-3: Diode, Zener, 10 V, 500 mW, SOD-123; Manufacturer: ON Semiconductor; SizeY_mm: 1.7; SizeX_mm: 3.85; RJA_CperW: 340; SizeAreaWB_mm2: 13.095; AEC Category: Q101; Power_W: 500mW; SizeZ_mm: 1.35; Value1: 0.5W; SizeArea_mm2: 6.545
D2 = CMP-0096356-1: Diode Array 1 Pair Series Connection Schottky 70 V 200mA (DC) Surface Mount TO-236-3, SC-59, SOT-23-3; Manufacturer: Vishay; ValueDisplayed: 1.5pF; TJmax_C: 125°C; AEC Qualified: No; Peak Reverse Current: 0.02uA; SizeZ_mm: 1.15mm; Max Surge Forward Current: 600mA
J1-J4 = CMP-0055387-2: Standard Banana Jack, Uninsulated, 15A; Manufacturer: Cinch Connectivity; CNHeader: FALSE; Green_Lifecycle: Active; Green_REACh: Passed; CT: TRUE
J5 J6 = CMP-0054801-2: Header, 2.54 mm, 6x1, Gold, TH; Manufacturer: Wurth Elektronik; Cert_UL: Y; Gender: Male; Row_Count: 1; Shrouded: N; Pitch_mm: 2.54
J7-J11 J13 J14 JP8 JP10-JP12 = CMP-0054794-2: Header, 2.54 mm, 2x1, Gold, TH; Manufacturer: Wurth Elektronik; Shrouded: N; Gender: Male; Green_REACh: Passed; Pitch_mm: 2.54; Green_Lifecycle: Active; Row_Count: 1; Cert_UL: Y
J12 = CMP-0055448-2: Header (shrouded), 100mil, 5x2, High-Temperature, Gold, TH; Manufacturer: 3M; Green_Lifecycle: Active; Green_REACh: Passed
JP1-JP3 JP5 JP7 JP9 = CMP-0054796-4: Header, 2.54 mm, 3x1, Gold, TH; Manufacturer: Wurth Elektronik; Green_Lifecycle: Active; Green_REACh: Passed; CT: FALSE; CNHeader: TRUE
JP4 = CMP-0055587-2: Header, 2.54mm, 3x2, Gold, TH; Manufacturer: Samtec; Green_Lifecycle: Active; Shrouded: N; Gender: Male; Cert_CSA: Y; Green_REACh: Passed; Row_Count: 2; RowSpacing_mm: 2.54
JP6 = CMP-0084909-1: Header, 2.54mm, 5x1, Gold, TH; Manufacturer: Wurth Elektronik; Pitch_mm: 2.54; Current_A: 3A; Shrouded: N; Gender: Male; Voltage_V: 250V; Row_Count: 1
L1 = CMP-0064042-1: Inductor, Shielded Drum Core, WE-Superflux200, 2.6 uH, 31.5 A, 0.0016 ohm, SMD; Manufacturer: Wurth Elektronik; Isat: 50A @ 30% inductance drop; Irms: 31.5A @ 50C rise; Green_Lifecycle: Active; SizeAreaWB_mm2: 410.06; DCR_ohm: 1.6m; Green_REACh: Passed; Value: 2.6uH; Imax_A: 31.5A; SizeZ_mm: 9.2; SizeX_mm: 18.3; SizeY_mm: 18.2; SizeArea_mm2: 333.06; Ind_H: 2.6µH; AEC Category: Q200
NT1 = CMP-0078142-6: Single point connection between nets.
Q1 Q1A Q2 Q2A Q3 Q3A Q4 Q4A = CMP-0124204-1: N-Channel 40 V 120A Surface Mount PG-TDSON-8-34; Manufacturer: Infineon; AEC Qualified: Yes; QgTyp_nC: 36nC @ 10V; Rdson45_ohm: 1.28m; SizeZ_mm: 1.1mm; VdsMax_V: 950mV; Vgs_V: 16V; AEC Grade: Grade 0; Drain To Source Breakdown Voltage: 40V; Input Capacitance At Vds: 2424pF @ 20V; Number Of Channels: 1; Power_W: 88W; Pulse Drain Current: 500A; Reverse Recovery Charge: 15nC; Reverse Recovery Time: 29ns; Rthja Max: 28K/W; Threshold Vgs Max: 1.8V; Threshold Vgs Min: 1.2V; TJmax_C: +175°C; Turn Off Delay Time: 21ns; Turn On Delay Time: 4ns; Typ Forward Diode Voltage: 0.8V
Q5 = CMP-0098297-1: Trans MOSFET P-CH -40V -100A 8-Pin SOIC - Tape and Reel; Manufacturer: Vishay; AEC Qualified: No; IdsMax_A: -31A; QgTyp_nC: 220nC @ -10V; Rdson45_ohm: 3m; SizeZ_mm: 1.12mm; VdsMax_V: -1.1V; Vgs_V: 20V; ChMode: False; Input Capacitace At Vds: 12900pF @ -20V; Number Of Channels: 1; Power_W: 6.25W; Pulse Drain Current: -200A; Reverse Recovery Charge: 39nC; Reverse Recovery Time: 41ns; Rthja Max: 15°C/W; Threshold Vgs Max: -2.3V; Threshold Vgs Min: -1V; TJmax_C: +150°C; Transconductance: 95S; Turn Off Delay Time: 125ns; Turn On Delay Time: 15ns; Typ Forward Diode Voltage: -0.73V
Q6 = CMP-0000823-2: MOSFET, N-CH, 60 V, 100 A, DNK0008A (VSON-CLIP-8); Alternate Manufacturer: None; Manufacturer: Texas Instruments; SizeZ_mm: 1; ChType: N; Value2: 41 nC; Value1: 0.003; VdsMax_V: 60V; SizeX_mm: 6; SizeY_mm: 5; Vgs_V: 20V; Value: 60V; Rdson45_ohm: 3.3m; SizeArea_mm2: 30; AEC Category: Q101; IdsMax_A: 100A; SizeAreaWB_mm2: 56; U/M: EA; QgTyp_nC: 41
R1 R2 = CMP-0095678-1: 4 mOhms ±1% 1W Chip Resistor Wide 0805 (2012 Metric), 0508 Automotive AEC-Q200, Current Sense Metal Foil; Manufacturer: Susumu; AEC Grade: Grade 0; TempCo: 50ppm/°C; AEC Qualified: Yes; SizeZ_mm: 0.7mm
R3 R4 = CMP-0090631-1: 3 mOhms ±1% 1W Chip Resistor Wide 0805 (2012 Metric), 0508 Automotive AEC-Q200, Current Sense Metal Foil; Manufacturer: Susumu; TempCo: 50ppm/°C; AEC Qualified: Yes; SizeZ_mm: 0.7mm; AEC Grade: Grade 0
R5 R6 R11 R12 R14 R16 R18 R22-R25 R34-R37 R56 R57 R61 R62 = CMP-0023343-3: RES, 0, 1%, 0.1 W, AEC-Q200 Grade 0, 0603; Manufacturer: Stackpole Electronics Inc; Power_W: 100mW; TempCo: ppm/C; U/M: EA; Value: 0; SizeX_mm: 1.6; SizeY_mm: 0.8; SizeZ_mm: 1; Value2: 0.1W; SizeArea_mm2: 1.28; AEC Qualified: Y; AEC Category: Q200
R7 R8 = CMP-0022004-4: RES, 10.0, 1%, 0.25 W, AEC-Q200 Grade 0, 0603; Manufacturer: Vishay-Dale; Power_W: 250mW; TempCo: 100 ppm/C; Value_Code: 10R0; Value: 10.0; EIA_Code: E96; Res_ohm: 10; SizeX_mm: 1.6; SizeY_mm: 0.8; SizeZ_mm: 1; Value2: 0.25W; SizeArea_mm2: 1.28; AEC Qualified: Y; VDC_V: 75V; AEC Category: Q200; AEC Grade: 0
R9 R20 = CMP-0023292-5: RES, 82.0 k, 1%, 0.1 W, 0603; Manufacturer: Yageo; Power_W: 100mW; TempCo: 100 ppm/C; Value_Code: 82k0; Value: 82.0k; Res_ohm: 82k; SizeX_mm: 1.6; SizeY_mm: 0.8; SizeZ_mm: 1; Value2: 0.1W; SizeArea_mm2: 1.28; AEC Qualified: N; VDC_V: 75V; AEC Category: Q200; SizeAreaWB_mm2: 4.68
R10 R21 = CMP-0022600-4: RES, 7.32 k, 1%, 0.1 W, AEC-Q200 Grade 0, 0603; Manufacturer: Vishay-Dale; Power_W: 100mW; TempCo: 100 ppm/C; Value_Code: 7k32; Value: 7.32k; EIA_Code: E96; SizeX_mm: 1.6; SizeY_mm: 0.8; SizeZ_mm: 1; Value2: 0.1W; SizeArea_mm2: 1.28; AEC Qualified: Y; VDC_V: 75V; AEC Category: Q200; AEC Grade: 0
R13 R63 = CMP-0022732-2: RES, 2.00, 1%, 0.125 W, 0603; Manufacturer: Vishay/Beyschlag; Power_W: 125mW; TempCo: 50 ppm/C; Value_Code: 2R00; U/M: EA; Value: 2.00; EIA_Code: E96; Res_ohm: 2; SizeX_mm: 1.6; SizeY_mm: 0.8; Value2: 0.125W; SizeArea_mm2: 1.28; AEC Qualified: N; AEC Category: Q200; SizeZ_mm: 1
R15 = CMP-0023267-5: RES, 75.0 k, 1%, 0.1 W, 0603; Manufacturer: Yageo; Power_W: 100mW; TempCo: 100 ppm/C; Value_Code: 75k0; Value: 75.0k; EIA_Code: E96; Res_ohm: 75k; SizeX_mm: 1.6; SizeY_mm: 0.8; SizeZ_mm: 1; Value2: 0.1W; SizeArea_mm2: 1.28; AEC Qualified: N; VDC_V: 75V; AEC Category: Q200; SizeAreaWB_mm2: 4.68
R17 = CMP-0022106-4: RES, 19.6 k, 1%, 0.1 W, AEC-Q200 Grade 0, 0603; Manufacturer: Vishay-Dale; Power_W: 100mW; TempCo: 100 ppm/C; Value_Code: 19k6; Value: 19.6k; EIA_Code: E96; SizeX_mm: 1.6; SizeY_mm: 0.8; SizeZ_mm: 1; Value2: 0.1W; SizeArea_mm2: 1.28; AEC Qualified: Y; VDC_V: 75V; AEC Category: Q200; AEC Grade: 0
R19 = CMP-0022751-4: RES, 10.0, 1%, 0.1 W, 0603; Manufacturer: Yageo; Power_W: 100mW; TempCo: 100 ppm/C; Value_Code: 10R0; Value: 10.0; EIA_Code: E96; Res_ohm: 10; SizeX_mm: 1.6; SizeY_mm: 0.8; SizeZ_mm: 1; Value2: 0.1W; SizeArea_mm2: 1.28; AEC Qualified: N; VDC_V: 75V; AEC Category: Q200; SizeAreaWB_mm2: 4.68
R26 = CMP-0023975-2: RES, 23.4 k, 0.1%, 0.1 W, 0603; Manufacturer: Yageo America; Power_W: 100mW; TempCo: 25 ppm/C; Value_Code: 23k4; U/M: EA; Value: 23.4k; EIA_Code: E192; SizeX_mm: 1.6; SizeY_mm: 0.8; SizeZ_mm: 1; Value2: 0.1W; SizeArea_mm2: 1.28; VDC_V: 75V; AEC Category: Q200
R27 R29 R47 = CMP-0023307-5: RES, 8.25 k, 1%, 0.1 W, 0603; Manufacturer: Yageo; Power_W: 100mW; TempCo: 100 ppm/C; Value_Code: 8k25; Value: 8.25k; EIA_Code: E96; SizeX_mm: 1.6; SizeY_mm: 0.8; SizeZ_mm: 1; Value2: 0.1W; SizeArea_mm2: 1.28; AEC Qualified: N; VDC_V: 75V; AEC Category: Q200; SizeAreaWB_mm2: 4.68
R28 R44 = CMP-0022381-4: RES, 3.83 k, 1%, 0.1 W, AEC-Q200 Grade 0, 0603; Manufacturer: Vishay-Dale; Power_W: 100mW; TempCo: 100 ppm/C; Value_Code: 3k83; Value: 3.83k; EIA_Code: E96; SizeX_mm: 1.6; SizeY_mm: 0.8; SizeZ_mm: 1; Value2: 0.1W; SizeArea_mm2: 1.28; AEC Qualified: Y; VDC_V: 75V; AEC Category: Q200; AEC Grade: 0
R30 = CMP-0022597-4: RES, 78.7 k, 1%, 0.1 W, AEC-Q200 Grade 0, 0603; Manufacturer: Vishay-Dale; Power_W: 100mW; TempCo: 100 ppm/C; Value_Code: 78k7; Value: 78.7k; EIA_Code: E96; SizeX_mm: 1.6; SizeY_mm: 0.8; SizeZ_mm: 1; Value2: 0.1W; SizeArea_mm2: 1.28; AEC Qualified: Y; VDC_V: 75V; AEC Category: Q200; AEC Grade: 0
R31 = CMP-0024307-2: RES, 50.5 k, 0.1%, 0.1 W, 0603; Manufacturer: Yageo America; Power_W: 100mW; TempCo: 25 ppm/C; Value_Code: 50k5; U/M: EA; Value: 50.5k; EIA_Code: E192; SizeX_mm: 1.6; SizeY_mm: 0.8; SizeZ_mm: 1; Value2: 0.1W; SizeArea_mm2: 1.28; VDC_V: 75V; AEC Category: Q200
R32 R48 = CMP-0022000-4: RES, 10.5 k, 1%, 0.1 W, AEC-Q200 Grade 0, 0603; Manufacturer: Vishay-Dale; Power_W: 100mW; TempCo: 100 ppm/C; Value_Code: 10k5; Value: 10.5k; EIA_Code: E96; SizeX_mm: 1.6; SizeY_mm: 0.8; SizeZ_mm: 1; Value2: 0.1W; SizeArea_mm2: 1.28; AEC Qualified: Y; VDC_V: 75V; AEC Category: Q200; AEC Grade: 0
R33 = CMP-0023653-3: RES, 10.0 k, 0.1%, 0.1 W, 0603; Manufacturer: Yageo America; Power_W: 100mW; TempCo: 25 ppm/C; Value_Code: 10k0; U/M: EA; Value: 10.0k; EIA_Code: E192; Res_ohm: 10k; SizeX_mm: 1.6; SizeY_mm: 0.8; SizeZ_mm: 1; Value2: 0.1W; SizeArea_mm2: 1.28; VDC_V: 75V; AEC Category: Q200
R38 = CMP-0025810-4: RES, 43 k, 5%, 0.1 W, AEC-Q200 Grade 0, 0603; Manufacturer: Vishay-Dale; Power_W: 100mW; TempCo: 200 ppm/C; Value_Code: 43k0; Value: 43k; EIA_Code: E24; SizeX_mm: 1.6; SizeY_mm: 0.8; SizeZ_mm: 1; Value2: 0.1W; SizeArea_mm2: 1.28; AEC Qualified: Y; VDC_V: 75V; AEC Category: Q200; AEC Grade: 0
R39 = CMP-0025725-4: RES, 180 k, 5%, 0.1 W, AEC-Q200 Grade 0, 0603; Manufacturer: Vishay-Dale; Power_W: 100mW; TempCo: 200 ppm/C; Value: 180k; EIA_Code: E24; SizeX_mm: 1.6; SizeY_mm: 0.8; SizeZ_mm: 1; Value2: 0.1W; SizeArea_mm2: 1.28; AEC Qualified: Y; VDC_V: 75V; AEC Category: Q200; AEC Grade: 0
R40 = CMP-0022481-5: RES, 511, 1%, 0.1 W, AEC-Q200 Grade 0, 0603; Manufacturer: Vishay-Dale; Power_W: 100mW; TempCo: 100 ppm/C; Value_Code: 511R; Value: 511; EIA_Code: E96; SizeX_mm: 1.6; SizeY_mm: 0.8; SizeZ_mm: 1; Value2: 0.1W; SizeArea_mm2: 1.28; AEC Qualified: Y; VDC_V: 75V; AEC Category: Q200; AEC Grade: 0
R41 = CMP-0022115-4: RES, 1.15 k, 1%, 0.1 W, AEC-Q200 Grade 0, 0603; Manufacturer: Vishay-Dale; Power_W: 100mW; TempCo: 100 ppm/C; Value_Code: 1k15; Value: 1.15k; EIA_Code: E96; SizeX_mm: 1.6; SizeY_mm: 0.8; SizeZ_mm: 1; Value2: 0.1W; SizeArea_mm2: 1.28; AEC Qualified: Y; VDC_V: 75V; AEC Category: Q200; AEC Grade: 0
R42 = CMP-0022891-5: RES, 1.87 k, 1%, 0.1 W, 0603; Manufacturer: Yageo; Power_W: 100mW; TempCo: 100 ppm/C; Value_Code: 1k87; Value: 1.87k; EIA_Code: E96; SizeX_mm: 1.6; SizeY_mm: 0.8; SizeZ_mm: 1; Value2: 0.1W; SizeArea_mm2: 1.28; AEC Qualified: N; VDC_V: 75V; AEC Category: Q200; SizeAreaWB_mm2: 4.68
R43 = CMP-0022996-5: RES, 2.70 k, 1%, 0.1 W, 0603; Manufacturer: Yageo; Power_W: 100mW; TempCo: 100 ppm/C; Value_Code: 2k70; Value: 2.70k; Res_ohm: 2.7k; SizeX_mm: 1.6; SizeY_mm: 0.8; SizeZ_mm: 1; Value2: 0.1W; SizeArea_mm2: 1.28; AEC Qualified: N; VDC_V: 75V; AEC Category: Q200; SizeAreaWB_mm2: 4.68
R45 R58 = CMP-0023198-5: RES, 5.10 k, 1%, 0.1 W, 0603; Manufacturer: Yageo; Power_W: 100mW; TempCo: 100 ppm/C; Value_Code: 5k10; Value: 5.10k; Res_ohm: 5.1k; SizeX_mm: 1.6; SizeY_mm: 0.8; SizeZ_mm: 1; Value2: 0.1W; SizeArea_mm2: 1.28; AEC Qualified: N; VDC_V: 75V; AEC Category: Q200; SizeAreaWB_mm2: 4.68
R46 = CMP-0023250-5: RES, 6.49 k, 1%, 0.1 W, 0603; Manufacturer: Yageo; Power_W: 100mW; TempCo: 100 ppm/C; Value_Code: 6k49; Value: 6.49k; EIA_Code: E96; SizeX_mm: 1.6; SizeY_mm: 0.8; SizeZ_mm: 1; Value2: 0.1W; SizeArea_mm2: 1.28; AEC Qualified: N; VDC_V: 75V; AEC Category: Q200; SizeAreaWB_mm2: 4.68
R49 = CMP-0022790-5: RES, 13.3 k, 1%, 0.1 W, 0603; Manufacturer: Yageo; Power_W: 100mW; TempCo: 100 ppm/C; Value_Code: 13k3; Value: 13.3k; EIA_Code: E96; SizeX_mm: 1.6; SizeY_mm: 0.8; SizeZ_mm: 1; Value2: 0.1W; SizeArea_mm2: 1.28; AEC Qualified: N; VDC_V: 75V; AEC Category: Q200; SizeAreaWB_mm2: 4.68
R50 = CMP-0022079-4: RES, 16.2 k, 1%, 0.1 W, AEC-Q200 Grade 0, 0603; Manufacturer: Vishay-Dale; Power_W: 100mW; TempCo: 100 ppm/C; Value_Code: 16k2; Value: 16.2k; EIA_Code: E96; SizeX_mm: 1.6; SizeY_mm: 0.8; SizeZ_mm: 1; Value2: 0.1W; SizeArea_mm2: 1.28; AEC Qualified: Y; VDC_V: 75V; AEC Category: Q200; AEC Grade: 0
R51 = CMP-0022905-5: RES, 20.5 k, 1%, 0.1 W, 0603; Manufacturer: Yageo; Power_W: 100mW; TempCo: 100 ppm/C; Value_Code: 20k5; Value: 20.5k; EIA_Code: E96; SizeX_mm: 1.6; SizeY_mm: 0.8; SizeZ_mm: 1; Value2: 0.1W; SizeArea_mm2: 1.28; AEC Qualified: N; VDC_V: 75V; AEC Category: Q200; SizeAreaWB_mm2: 4.68
R52 = CMP-0022237-4: RES, 24.9 k, 1%, 0.1 W, AEC-Q200 Grade 0, 0603; Manufacturer: Vishay-Dale; Power_W: 100mW; TempCo: 100 ppm/C; Value_Code: 24k9; Value: 24.9k; EIA_Code: E96; SizeX_mm: 1.6; SizeY_mm: 0.8; SizeZ_mm: 1; Value2: 0.1W; SizeArea_mm2: 1.28; AEC Qualified: Y; VDC_V: 75V; AEC Category: Q200; AEC Grade: 0
R53 = CMP-0022324-4: RES, 30.1 k, 1%, 0.1 W, AEC-Q200 Grade 0, 0603; Manufacturer: Vishay-Dale; Power_W: 100mW; TempCo: 100 ppm/C; Value_Code: 30k1; Value: 30.1k; EIA_Code: E96; SizeX_mm: 1.6; SizeY_mm: 0.8; SizeZ_mm: 1; Value2: 0.1W; SizeArea_mm2: 1.28; AEC Qualified: Y; VDC_V: 75V; AEC Category: Q200; AEC Grade: 0
R54 = CMP-0022352-4: RES, 35.7 k, 1%, 0.1 W, AEC-Q200 Grade 0, 0603; Manufacturer: Vishay-Dale; Power_W: 100mW; TempCo: 100 ppm/C; Value_Code: 35k7; Value: 35.7k; EIA_Code: E96; SizeX_mm: 1.6; SizeY_mm: 0.8; SizeZ_mm: 1; Value2: 0.1W; SizeArea_mm2: 1.28; AEC Qualified: Y; VDC_V: 75V; AEC Category: Q200; AEC Grade: 0
R55 = CMP-0025771-4: RES, 2.7 k, 5%, 0.1 W, AEC-Q200 Grade 0, 0603; Manufacturer: Vishay-Dale; Power_W: 100mW; TempCo: 200 ppm/C; Value_Code: 2k70; Value: 2.7k; EIA_Code: E24; SizeX_mm: 1.6; SizeY_mm: 0.8; SizeZ_mm: 1; Value2: 0.1W; SizeArea_mm2: 1.28; AEC Qualified: Y; VDC_V: 75V; AEC Category: Q200; AEC Grade: 0
R59 R60 = CMP-0025804-4: RES, 3.0, 5%, 0.1 W, AEC-Q200 Grade 0, 0603; Manufacturer: Vishay-Dale; Power_W: 100mW; TempCo: 200 ppm/C; Value_Code: 3R00; Value: 3.0; EIA_Code: E24; Res_ohm: 3; SizeX_mm: 1.6; SizeY_mm: 0.8; SizeZ_mm: 1; Value2: 0.1W; SizeArea_mm2: 1.28; AEC Qualified: Y; VDC_V: 75V; AEC Category: Q200; AEC Grade: 0
R64 R65 = CMP-0023000-5: RES, 2.00 k, 1%, 0.1 W, 0603; Manufacturer: Yageo; Power_W: 100mW; TempCo: 100 ppm/C; Value_Code: 2k00; Value: 2.00k; EIA_Code: E96; Res_ohm: 2k; SizeX_mm: 1.6; SizeY_mm: 0.8; SizeZ_mm: 1; Value2: 0.1W; SizeArea_mm2: 1.28; AEC Qualified: N; VDC_V: 75V; AEC Category: Q200; SizeAreaWB_mm2: 4.68
S1 S2 = CMP-0002229-1: Switch, SPST, 8 Pos, 25mA, 24VDC, SMD; Manufacturer: CTS Electrocomponents; CurrentRating_mA: 25A; PositionCount: 8; VDC_V: 24V; SwitchFunction: Off-On
TP1 TP2 = CMP-0055147-2: Test Point, Multipurpose, Red, TH; Manufacturer: Keystone Electronics; CNHeader: FALSE; Green_Lifecycle: Active; Green_REACh: Passed; ContactFinish: Silver; CT: TRUE
TP3 TP4 = CMP-0055148-2: Test Point, Multipurpose, Black, TH; Manufacturer: Keystone Electronics; CNHeader: FALSE; Green_Lifecycle: Active; Green_REACh: Passed; ContactFinish: Silver; CT: TRUE
TP5 TP6 = CMP-0067619-1: Natural PC Test Point Brass, SMT; Manufacturer: Harwin
TP7 TP8 = CMP-0055150-2: Test Point, Multipurpose, Orange, TH; Manufacturer: Keystone Electronics; CNHeader: FALSE; Green_Lifecycle: Active; Green_REACh: Passed; ContactFinish: Silver; CT: TRUE
TP9 TP14 = CMP-0055138-2: Test Point, Miniature, Black, TH; Manufacturer: Keystone Electronics; CNHeader: FALSE; Green_Lifecycle: Active; Green_REACh: Passed; ContactFinish: Silver; CT: TRUE
TP10-TP13 TP15 = CMP-0055141-2: Test Point, Miniature, Yellow, TH; Manufacturer: Keystone Electronics; CNHeader: FALSE; Green_Lifecycle: Active; Green_REACh: Passed; ContactFinish: Silver; CT: TRUE
U1 = CMP-0124597-1: 48-V 4 Switch Buck-Boost Controller with I2C interface; Manufacturer: Texas Instruments; SizeZ_mm: 1mm; AEC Qualified: Yes; AEC Grade: Grade 0; Max Supply Voltage: 48V; Min Supply Voltage: 3.3V; Nominal Supply Current: 25uA; Number Of Outputs: 1; Output Type: AdjustableProgrammable; Output Voltage: 3.3-48V; Standoff Height: 0mm; Switching Frequency: 100-2200kHz; TJmax_C: +150°C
